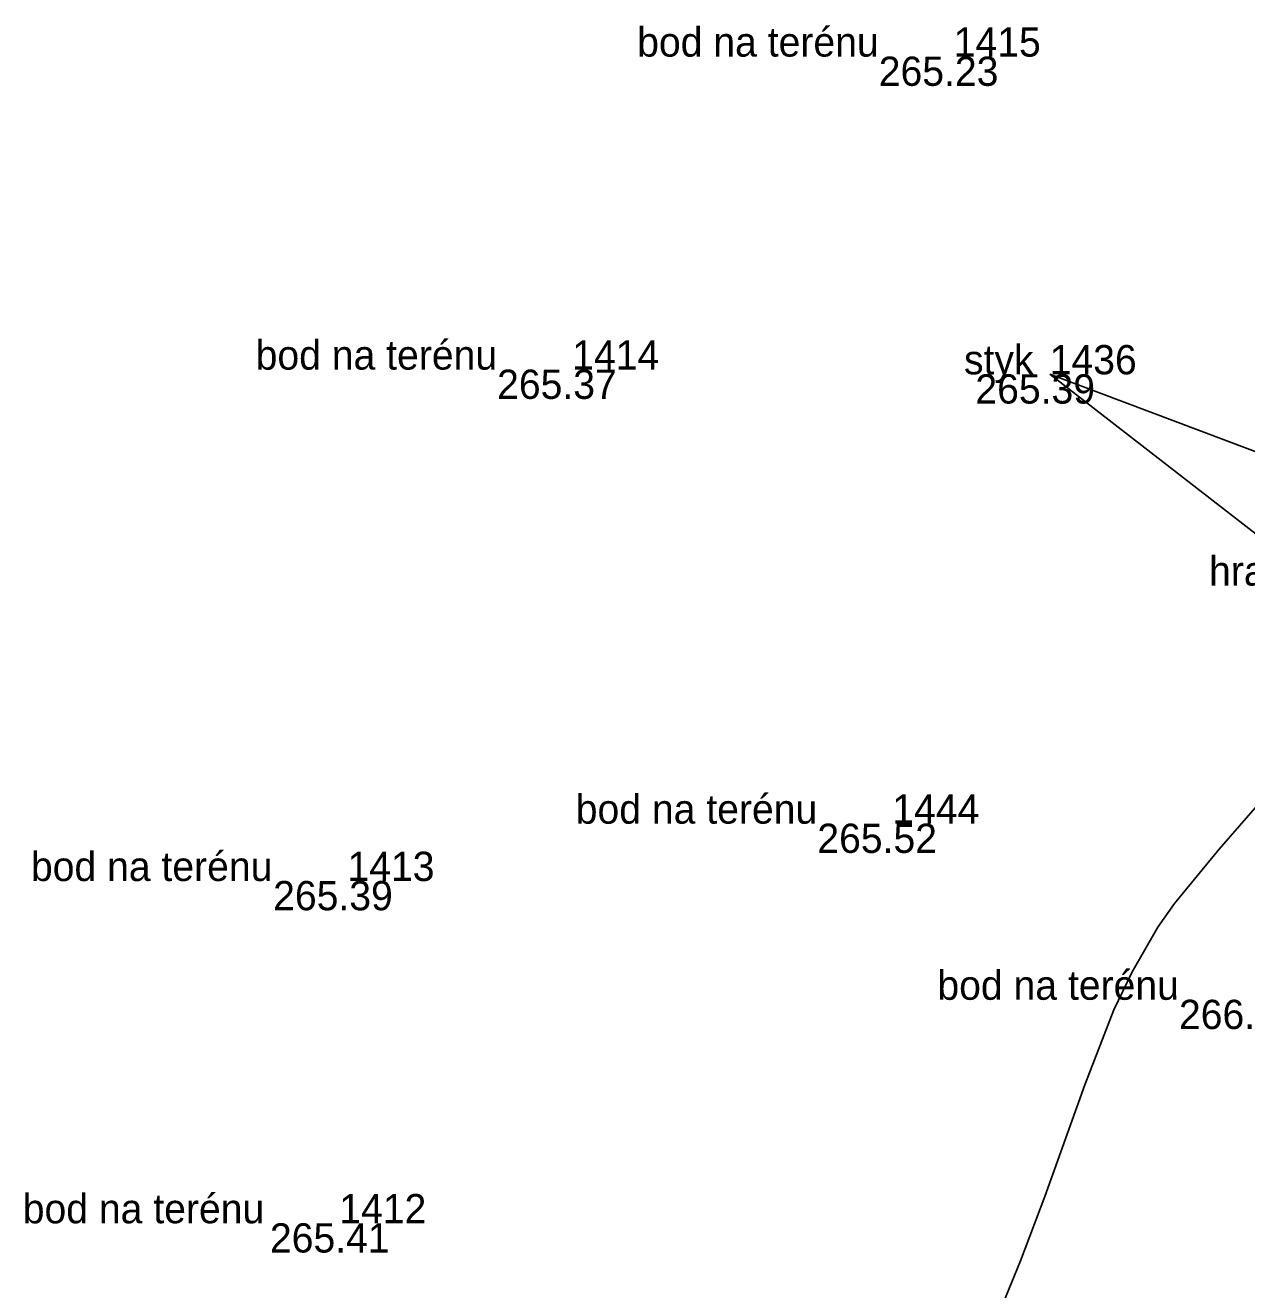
# Model space of a CAD drawing. Extents: x -567962 to -566460, y -1093720 to -1089838.
# Drawn here: x -567160.72 to -567139.84, y -1090786.66 to -1090765.04 of the extents above; entities that cross this region are included whole.
import ezdxf

# ---------------------------------------------------------------- set-up
doc = ezdxf.new("R2010")
doc.units = 0
for name, color, linetype in [('bod_znacka', 7, 'Continuous'), ('cislo_bodu', 7, 'Continuous'), ('hrana_L', 7, 'Continuous'), ('kod_bodu', 7, 'Continuous'), ('norm_vrst', 7, 'Continuous'), ('vyska_bodu', 7, 'Continuous')]:
    doc.layers.add(name, color=color, linetype=linetype)

msp = doc.modelspace()

# ---------------------------------------------------------------- linework, layer by layer
at = {"layer": 'bod_znacka'}
for p, q in [((-567144.85, -1090765.58), (-567144.85, -1090765.58)), ((-567151.37, -1090770.93), (-567151.37, -1090770.93)), ((-567143.21, -1090771.01), (-567143.21, -1090771.01)), ((-567145.9, -1090778.69), (-567145.9, -1090778.69)), ((-567155.21, -1090779.67), (-567155.21, -1090779.67)), ((-567155.35, -1090785.52), (-567155.35, -1090785.52))]:
    msp.add_line(p, q, dxfattribs=at)
at = {"layer": 'hrana_L'}
for p, q in [((-567143.21, -1090771.01), (-567137.49, -1090773.16)), ((-567138.55, -1090774.62), (-567143.21, -1090771.01))]:
    msp.add_line(p, q, dxfattribs=at)
at = {"layer": 'norm_vrst'}
msp.add_lwpolyline([(-567138.926, -1090777.529), (-567140.312, -1090779.127), (-567141.076, -1090780.052), (-567141.36, -1090780.457), (-567141.807, -1090781.232), (-567142.113, -1090781.873), (-567142.609, -1090783.152), (-567143.294, -1090785.064), (-567143.707, -1090786.163), (-567144.168, -1090787.289)], dxfattribs=at)

# ---------------------------------------------------------------- texts
at = {"layer": 'cislo_bodu'}
for s, p in [('1415', (-567144.85, -1090765.58)), ('1414', (-567151.37, -1090770.93)), ('1436', (-567143.21, -1090771.01)), ('1444', (-567145.9, -1090778.69)), ('1413', (-567155.21, -1090779.67)), ('1412', (-567155.35, -1090785.52))]:
    msp.add_text(s, height=0.5, dxfattribs=at).set_placement(p)
at = {"layer": 'kod_bodu'}
for s, p in [('bod na terénu', (-567150.259, -1090765.58)), ('bod na terénu', (-567156.779, -1090770.93)), ('styk', (-567144.674, -1090771.01)), ('hrana', (-567140.487, -1090774.62)), ('bod na terénu', (-567151.309, -1090778.69)), ('bod na terénu', (-567160.619, -1090779.67)), ('bod na terénu', (-567145.129, -1090781.7)), ('bod na terénu', (-567160.759, -1090785.52))]:
    msp.add_text(s, height=0.5, dxfattribs=at).set_placement(p)
at = {"layer": 'vyska_bodu'}
for s, p in [('265.23', (-567146.131, -1090766.08)), ('265.37', (-567152.653, -1090771.43)), ('265.39', (-567144.48, -1090771.51)), ('265.52', (-567147.181, -1090779.19)), ('265.39', (-567156.48, -1090780.17)), ('266.24', (-567141.001, -1090782.2)), ('265.41', (-567156.535, -1090786.02))]:
    msp.add_text(s, height=0.5, dxfattribs=at).set_placement(p)

doc.saveas('drawing.dxf')
